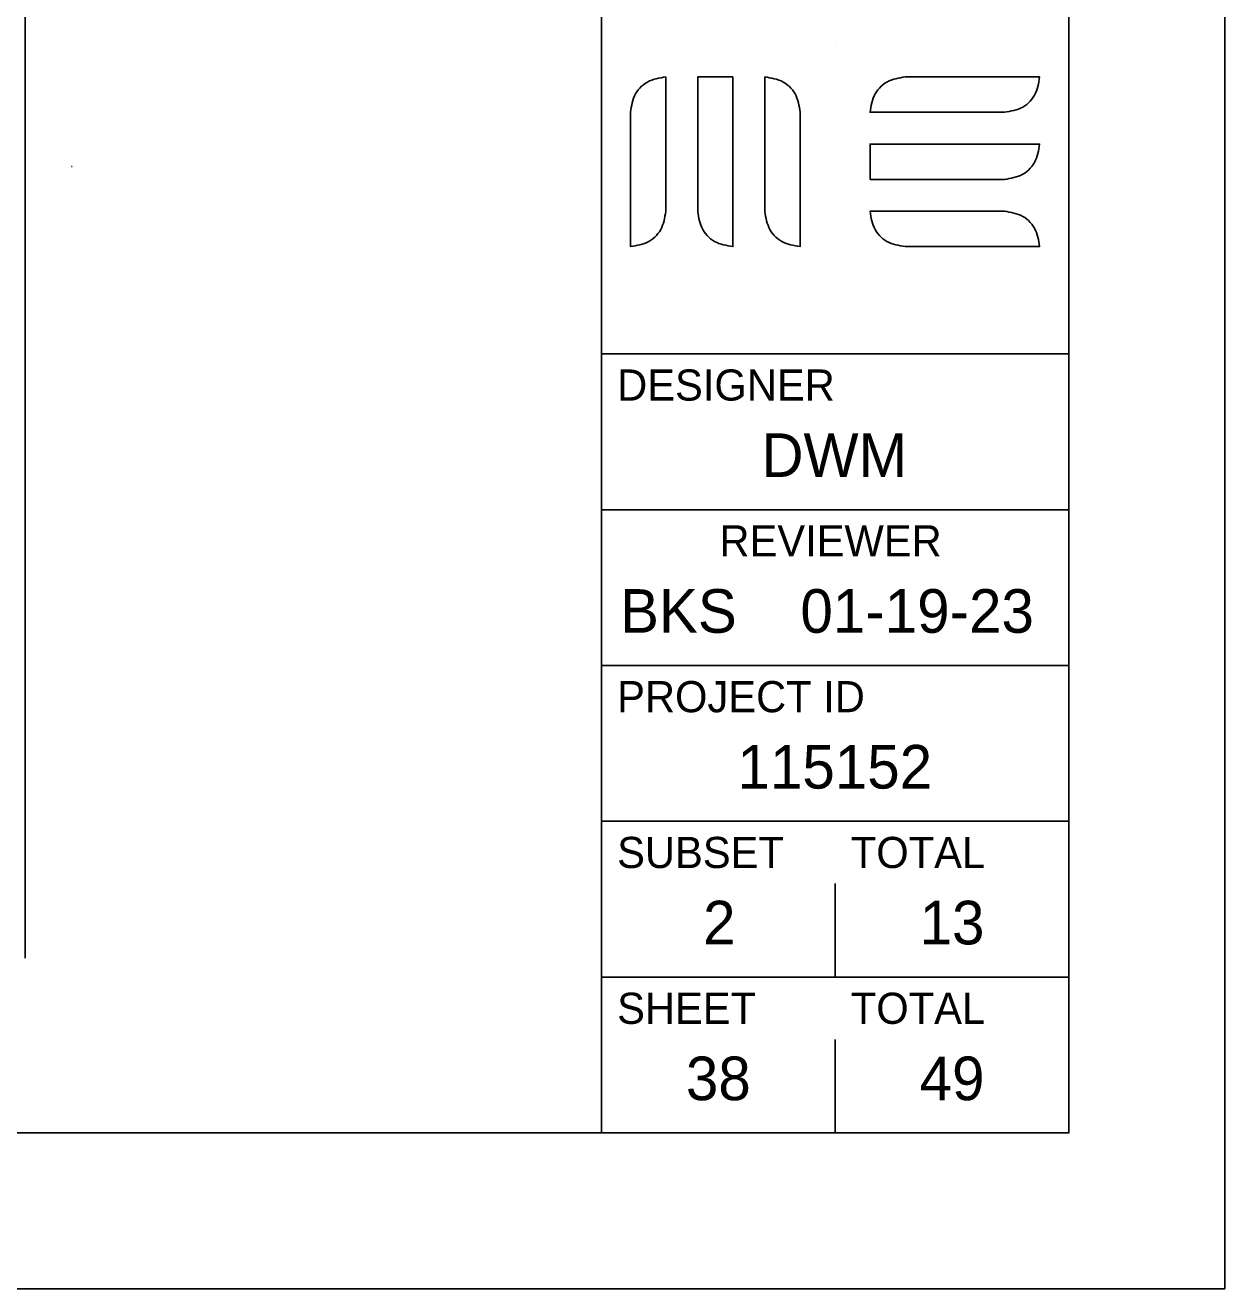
# Model space of a CAD drawing. Extents: x -2280229 to 1306, y -58886 to 440.
# Drawn here: x 603 to 680, y 0 to 81.1 of the extents above; entities that cross this region are included whole.
import ezdxf

# ---------------------------------------------------------------- set-up
doc = ezdxf.new("R2010")
doc.units = 0
for name, color, linetype in [('GT_Project_Cells', 7, 'Continuous'), ('GT_Project_Soil_Boring', 7, 'Continuous'), ('GT_Project_Text', 7, 'Continuous'), ('PF_X_Ground_Line', 7, 'Continuous'), ('SC_Scratch1', 7, 'Continuous'), ('SC_Scratch5', 7, 'Continuous')]:
    doc.layers.add(name, color=color, linetype=linetype)

msp = doc.modelspace()

# ---------------------------------------------------------------- linework, layer by layer
at = {"layer": 'GT_Project_Cells'}
for p, q in [((655, 80), (655, 80)), ((655, 80), (655, 80)), ((655, 20), (655, 26)), ((655, 10), (655, 16)), ((647.5, 13.5), (647.5, 13.5))]:
    msp.add_line(p, q, dxfattribs=at)
at = {"layer": 'GT_Project_Soil_Boring'}
for points in [[(644.121, 77.774), (643.968, 77.75), (643.815, 77.724), (643.663, 77.695), (643.513, 77.661), (643.366, 77.621), (643.221, 77.573), (643.08, 77.515), (642.944, 77.446), (642.813, 77.366), (642.687, 77.275), (642.569, 77.173), (642.459, 77.063), (642.357, 76.944), (642.266, 76.819), (642.185, 76.688), (642.117, 76.551), (642.059, 76.411), (642.011, 76.266), (641.971, 76.119), (641.937, 75.969), (641.908, 75.817), (641.882, 75.664), (641.857, 75.511), (641.857, 66.887), (642.011, 66.912), (642.164, 66.938), (642.316, 66.967), (642.466, 67.001), (642.613, 67.041), (642.757, 67.089), (642.898, 67.147), (643.035, 67.215), (643.166, 67.296), (643.291, 67.387), (643.41, 67.488), (643.52, 67.599), (643.621, 67.717), (643.713, 67.842), (643.793, 67.974), (643.862, 68.11), (643.92, 68.251), (643.968, 68.395), (644.008, 68.543), (644.042, 68.693), (644.071, 68.844), (644.097, 68.997), (644.121, 69.151), (644.121, 77.774)], [(648.433, 77.774), (646.169, 77.774), (646.169, 69.151), (646.194, 68.997), (646.22, 68.844), (646.249, 68.693), (646.283, 68.543), (646.323, 68.395), (646.371, 68.251), (646.428, 68.11), (646.497, 67.974), (646.577, 67.842), (646.669, 67.717), (646.77, 67.599), (646.881, 67.488), (646.999, 67.387), (647.124, 67.296), (647.256, 67.215), (647.392, 67.147), (647.533, 67.089), (647.677, 67.041), (647.825, 67.001), (647.975, 66.967), (648.126, 66.938), (648.279, 66.912), (648.433, 66.887), (648.433, 77.774)], [(652.745, 75.511), (652.72, 75.664), (652.694, 75.817), (652.665, 75.969), (652.631, 76.119), (652.591, 76.266), (652.543, 76.411), (652.485, 76.551), (652.417, 76.688), (652.336, 76.819), (652.245, 76.944), (652.144, 77.063), (652.033, 77.173), (651.915, 77.275), (651.789, 77.366), (651.658, 77.446), (651.522, 77.515), (651.381, 77.573), (651.237, 77.621), (651.089, 77.661), (650.939, 77.695), (650.787, 77.724), (650.634, 77.75), (650.481, 77.774), (650.481, 69.151), (650.505, 68.997), (650.531, 68.844), (650.56, 68.693), (650.594, 68.543), (650.634, 68.395), (650.683, 68.251), (650.74, 68.11), (650.809, 67.974), (650.889, 67.842), (650.981, 67.717), (651.082, 67.599), (651.192, 67.488), (651.311, 67.387), (651.436, 67.296), (651.567, 67.215), (651.704, 67.147), (651.845, 67.089), (651.989, 67.041), (652.136, 67.001), (652.286, 66.967), (652.438, 66.938), (652.591, 66.912), (652.745, 66.887), (652.745, 75.511)], [(667.62, 76.34), (667.711, 76.466), (667.791, 76.597), (667.86, 76.734), (667.918, 76.874), (667.966, 77.019), (668.006, 77.166), (668.04, 77.316), (668.069, 77.468), (668.095, 77.621), (668.119, 77.774), (659.496, 77.774), (659.342, 77.75), (659.189, 77.724), (659.038, 77.695), (658.888, 77.661), (658.74, 77.621), (658.596, 77.573), (658.455, 77.515), (658.319, 77.446), (658.187, 77.366), (658.062, 77.275), (657.944, 77.173), (657.833, 77.063), (657.732, 76.944), (657.64, 76.819), (657.56, 76.688), (657.491, 76.551), (657.434, 76.411), (657.386, 76.266), (657.345, 76.119), (657.312, 75.969), (657.282, 75.817), (657.256, 75.664), (657.232, 75.511), (665.856, 75.511), (666.009, 75.535), (666.162, 75.561), (666.314, 75.59), (666.464, 75.624), (666.611, 75.664), (666.756, 75.712), (666.896, 75.77), (667.033, 75.838), (667.164, 75.919), (667.289, 76.01), (667.408, 76.112), (667.518, 76.222), (667.62, 76.34)], [(667.918, 72.563), (667.966, 72.707), (668.006, 72.854), (668.04, 73.004), (668.069, 73.156), (668.095, 73.309), (668.119, 73.463), (657.232, 73.463), (657.232, 71.199), (665.856, 71.199), (666.009, 71.223), (666.162, 71.249), (666.314, 71.278), (666.464, 71.312), (666.611, 71.353), (666.756, 71.401), (666.896, 71.458), (667.033, 71.527), (667.164, 71.607), (667.289, 71.699), (667.408, 71.8), (667.518, 71.91), (667.62, 72.029), (667.711, 72.154), (667.791, 72.286), (667.86, 72.422), (667.918, 72.563)], [(667.966, 67.643), (667.918, 67.787), (667.86, 67.928), (667.791, 68.064), (667.711, 68.196), (667.62, 68.321), (667.518, 68.44), (667.408, 68.55), (667.289, 68.651), (667.164, 68.743), (667.033, 68.823), (666.896, 68.892), (666.756, 68.949), (666.611, 68.997), (666.464, 69.038), (666.314, 69.071), (666.162, 69.101), (666.009, 69.127), (665.856, 69.151), (657.232, 69.151), (657.256, 68.997), (657.282, 68.844), (657.312, 68.693), (657.345, 68.543), (657.386, 68.395), (657.434, 68.251), (657.491, 68.11), (657.56, 67.974), (657.64, 67.842), (657.732, 67.717), (657.833, 67.599), (657.944, 67.488), (658.062, 67.387), (658.187, 67.296), (658.319, 67.215), (658.455, 67.147), (658.596, 67.089), (658.74, 67.041), (658.888, 67.001), (659.038, 66.967), (659.189, 66.938), (659.342, 66.912), (659.496, 66.887), (668.119, 66.887), (668.095, 67.041), (668.069, 67.194), (668.04, 67.346), (668.006, 67.496), (667.966, 67.643)]]:
    msp.add_lwpolyline(points, dxfattribs=at)
at = {"layer": 'GT_Project_Text'}
msp.add_lwpolyline([(0, 0), (680, 0), (680, 440), (0, 440)], close=True, dxfattribs=at)
at = {"layer": 'PF_X_Ground_Line'}
msp.add_line((605.974, 72.017), (606.019, 72.016), dxfattribs=at)
at = {"layer": 'SC_Scratch1'}
for p, q in [((640, 10), (640, 430)), ((640, 60), (670, 60)), ((640, 50), (670, 50)), ((640, 40), (670, 40)), ((640, 30), (670, 30)), ((640, 20), (670, 20))]:
    msp.add_line(p, q, dxfattribs=at)
msp.add_lwpolyline([(30, 430), (670, 430), (670, 10), (30, 10)], close=True, dxfattribs=at)
at = {"layer": 'SC_Scratch5'}
msp.add_line((603.007, 21.221), (603.007, 162.208), dxfattribs=at)

# ---------------------------------------------------------------- texts
at = {"layer": 'GT_Project_Cells'}
for s, height, p in [('DESIGNER', 2, (641, 57)), ('DWM', 2.8, (650.259, 52.1)), ('REVIEWER', 2, (647.566, 47)), ('BKS', 2.8, (641.187, 42.1)), ('01-19-23', 2.8, (652.763, 42.1)), ('PROJECT ID', 2, (641, 37)), ('115152', 2.8, (648.725, 32.1)), ('SUBSET', 2, (641, 27)), ('TOTAL', 2, (656, 27)), ('2', 2.8, (646.516, 22.1)), ('13', 2.8, (660.414, 22.1)), ('SHEET', 2, (641, 17)), ('TOTAL', 2, (656, 17)), ('38', 2.8, (645.412, 12.1)), ('49', 2.8, (660.412, 12.1))]:
    msp.add_text(s, height=height, dxfattribs=at).set_placement(p)

doc.saveas('drawing.dxf')
